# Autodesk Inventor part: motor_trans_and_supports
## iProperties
Created: 2007-01
Part Number: motor_trans_and_supports
Document SubType Name: Modeling
Density: 1 g/cm^3
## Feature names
1. Extrusion1
2. Extrusion2
3. Extrusion9
4. Hole10
5. Extrusion10
6. Hole9
